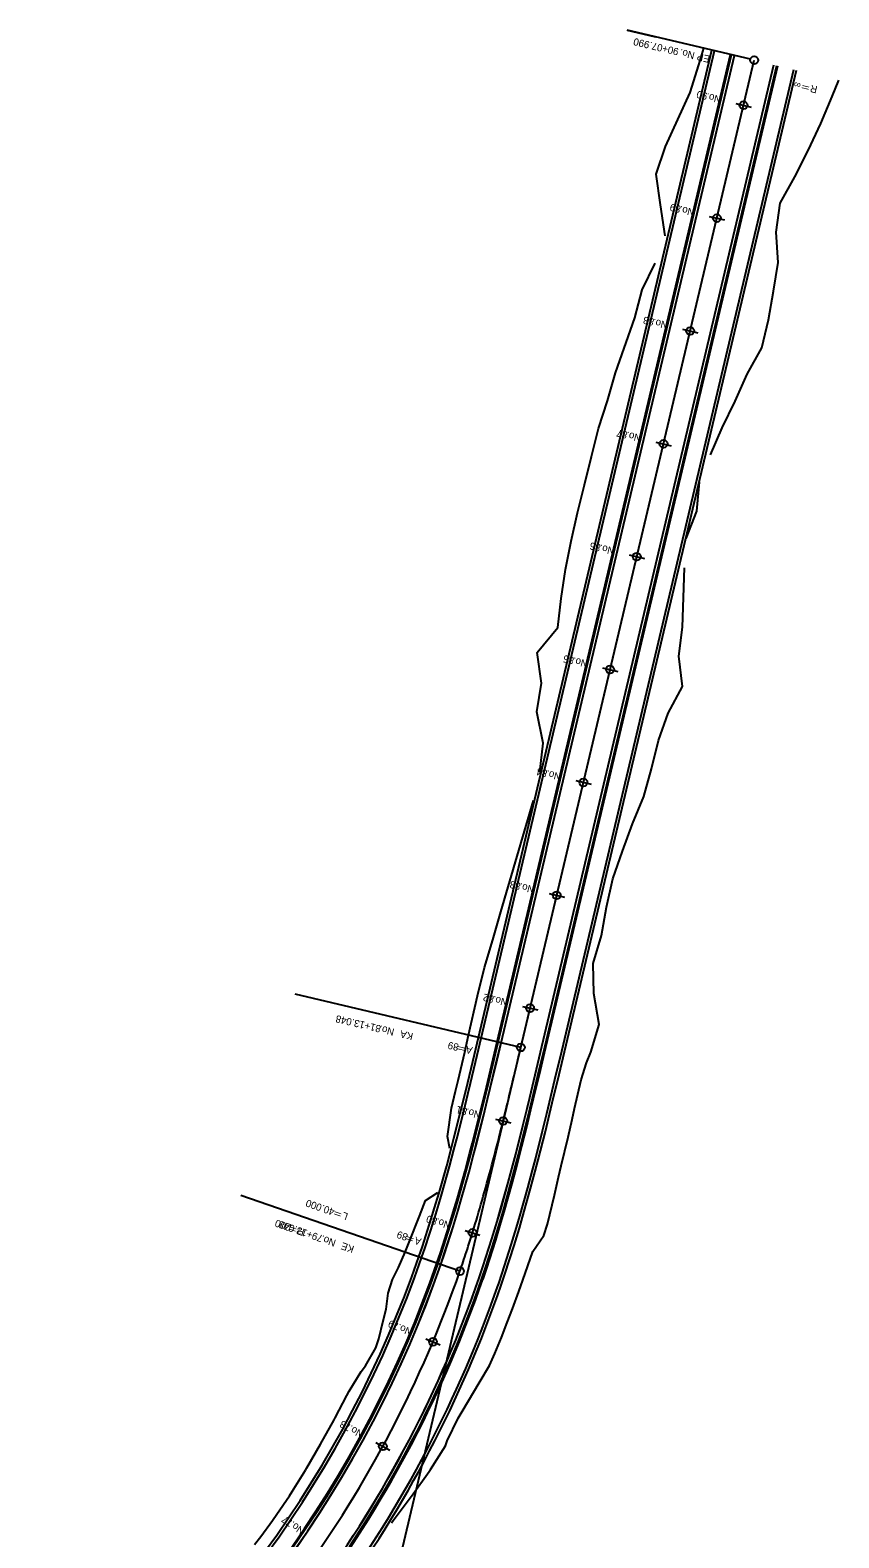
# Model space of a CAD drawing. Extents: x 46424 to 47578, y 10417 to 11548.
# Drawn here: x 47438.6 to 47578.1, y 11288 to 11548 of the extents above; entities that cross this region are included whole.
import ezdxf

# ---------------------------------------------------------------- set-up
doc = ezdxf.new("R2010")
doc.units = 0
for name, color, linetype in [('Default', 7, 'Continuous'), ('出典（地理院地図Vector）', 7, 'Continuous'), ('河川_人工水路(地下)（地理院地図Vector）', 7, 'Continuous'), ('現況_地形', 7, 'Continuous'), ('現況_地形_三角形', 7, 'Continuous'), ('現況_地形_三角形_頂点', 7, 'Continuous'), ('現況_地形_低い点', 7, 'Continuous'), ('現況_地形_単点標高', 7, 'Continuous'), ('現況_地形_等高線_マイナー', 7, 'Continuous'), ('等高線等深線_等高線_補助曲線通常部（地理院地図Vector）', 7, 'Continuous'), ('設計図面_測点 ラベル メジャー', 7, 'Continuous'), ('設計図面_測点 印 メジャー', 7, 'Continuous')]:
    doc.layers.add(name, color=color, linetype=linetype)

msp = doc.modelspace()

# ---------------------------------------------------------------- linework, layer by layer
at = {"layer": 'Default'}
for p, q in [((47562.82, 11542.97), (47541.58, 11547.99)), ((47541.58, 11547.99), (47546.44, 11546.84)), ((47499.18, 11270.82), (47563.47, 11542.81)), ((47523.23, 11372.56), (47563.47, 11542.81)), ((47563.47, 11542.81), (47563.47, 11542.81)), ((47561.64, 11535.04), (47561.64, 11535.04)), ((47557.04, 11515.57), (47557.04, 11515.57)), ((47552.44, 11496.11), (47552.44, 11496.11)), ((47547.84, 11476.65), (47547.84, 11476.65)), ((47543.23, 11457.18), (47543.23, 11457.18)), ((47538.63, 11437.72), (47538.63, 11437.72)), ((47534.03, 11418.25), (47534.03, 11418.25)), ((47529.43, 11398.79), (47529.43, 11398.79)), ((47523.23, 11372.56), (47484.31, 11381.76)), ((47524.83, 11379.33), (47524.83, 11379.33)), ((47523.23, 11372.56), (47523.23, 11372.56)), ((47520.19, 11359.87), (47520.19, 11359.87)), ((47512.74, 11333.98), (47474.93, 11347.02)), ((47512.74, 11333.98), (47474.93, 11347.02)), ((47514.9, 11340.59), (47514.9, 11340.59)), ((47512.74, 11333.98), (47512.74, 11333.98)), ((47508.09, 11321.79), (47508.09, 11321.79)), ((47499.44, 11303.77), (47499.44, 11303.77))]:
    msp.add_line(p, q, dxfattribs=at)
for centre in [(47563.47, 11542.81), (47561.64, 11535.04), (47557.04, 11515.57), (47552.44, 11496.11), (47547.84, 11476.65), (47543.23, 11457.18), (47538.63, 11437.72), (47534.03, 11418.25), (47529.43, 11398.79), (47524.83, 11379.33), (47523.23, 11372.56), (47520.19, 11359.87), (47514.9, 11340.59), (47512.74, 11333.98), (47508.09, 11321.79), (47499.44, 11303.77)]:
    msp.add_circle(centre, 0.675, dxfattribs=at)
msp.add_arc((47323.67, 11399.19), 200, 306.6653, 340.9717, dxfattribs=at)
msp.add_arc((47323.67, 11399.19), 200, 306.6653, 340.9717, dxfattribs=at)
msp.add_open_spline([(47512.74, 11333.98), (47513.11, 11335.03), (47513.81, 11337.14), (47515.16, 11341.37), (47516.74, 11346.7), (47518.49, 11353.13), (47520.13, 11359.59), (47521.44, 11364.99), (47522.47, 11369.32), (47522.98, 11371.48), (47523.23, 11372.56)], degree=3, dxfattribs=at)
msp.add_open_spline([(47512.74, 11333.98), (47513.11, 11335.03), (47513.81, 11337.14), (47515.16, 11341.37), (47516.74, 11346.7), (47518.49, 11353.13), (47520.13, 11359.59), (47521.44, 11364.99), (47522.47, 11369.32), (47522.98, 11371.48), (47523.23, 11372.56)], degree=3, dxfattribs=at)
at = {"layer": '出典（地理院地図Vector）'}
for points in [[(47505.65, 11336.42), (47506.26, 11338.21), (47507.74, 11342.81), (47508.6, 11345.64), (47509.13, 11347.46), (47510.45, 11352.16), (47511.22, 11355.04), (47511.7, 11356.9), (47512.91, 11361.68), (47513.62, 11364.61), (47514.08, 11366.49), (47515.23, 11371.32), (47515.93, 11374.29), (47556.18, 11544.54)], [(47519.83, 11331.53), (47520.49, 11333.45), (47522.07, 11338.37), (47522.98, 11341.37), (47523.54, 11343.3), (47524.92, 11348.23), (47525.72, 11351.23), (47526.22, 11353.15), (47527.47, 11358.07), (47528.2, 11361.06), (47528.66, 11362.98), (47529.83, 11367.87), (47530.53, 11370.84), (47570.77, 11541.09)]]:
    msp.add_lwpolyline(points, dxfattribs=at)
for radius in [192.5, 207.5]:
    msp.add_arc((47323.67, 11399.19), radius, 306.6653, 340.9717, dxfattribs=at)
at = {"layer": '河川_人工水路(地下)（地理院地図Vector）'}
msp.add_line((47523.23, 11372.56), (47563.47, 11542.81), dxfattribs=at)
msp.add_arc((47323.67, 11399.19), 200, 306.6653, 340.9717, dxfattribs=at)
msp.add_open_spline([(47512.74, 11333.98), (47513.11, 11335.03), (47513.81, 11337.14), (47515.16, 11341.37), (47516.74, 11346.7), (47518.49, 11353.13), (47520.13, 11359.59), (47521.44, 11364.99), (47522.47, 11369.32), (47522.98, 11371.48), (47523.23, 11372.56)], degree=3, dxfattribs=at)
at = {"layer": '現況_地形'}
for points in [[(47509.43, 11335.12), (47510.04, 11336.94), (47511.55, 11341.63), (47512.42, 11344.5), (47512.96, 11346.35), (47514.3, 11351.11), (47515.08, 11354.03), (47515.56, 11355.9), (47516.78, 11360.72), (47517.5, 11363.66), (47517.96, 11365.55), (47519.12, 11370.4), (47519.82, 11373.37), (47560.06, 11543.62)], [(47509.44, 11335.12), (47510.05, 11336.94), (47511.56, 11341.62), (47512.43, 11344.5), (47512.97, 11346.35), (47514.31, 11351.11), (47515.09, 11354.03), (47515.57, 11355.9), (47516.79, 11360.72), (47517.51, 11363.66), (47517.97, 11365.55), (47519.13, 11370.4), (47519.83, 11373.37), (47560.07, 11543.62)], [(47516.05, 11332.84), (47516.69, 11334.72), (47518.25, 11339.55), (47519.14, 11342.51), (47519.7, 11344.41), (47521.06, 11349.27), (47521.86, 11352.25), (47522.35, 11354.15), (47523.58, 11359.03), (47524.31, 11362.01), (47524.77, 11363.91), (47525.94, 11368.79), (47526.64, 11371.76), (47566.88, 11542.01)], [(47516.06, 11332.84), (47516.7, 11334.71), (47518.26, 11339.55), (47519.15, 11342.51), (47519.71, 11344.4), (47521.07, 11349.27), (47521.87, 11352.24), (47522.36, 11354.15), (47523.59, 11359.03), (47524.32, 11362.01), (47524.78, 11363.91), (47525.95, 11368.79), (47526.65, 11371.75), (47566.89, 11542)]]:
    msp.add_lwpolyline(points, dxfattribs=at)
for radius in [196.5, 196.49, 203.5, 203.51]:
    msp.add_arc((47323.67, 11399.19), radius, 306.6653, 340.9717, dxfattribs=at)
at = {"layer": '現況_地形_三角形'}
for points in [[(47548.14, 11512.54), (47547.32, 11517.87), (47546.6, 11523.18), (47548.17, 11527.94), (47552.45, 11537.21), (47553.94, 11541.99), (47554.79, 11544.87)], [(47551.75, 11460.31), (47553.57, 11465.01), (47554.02, 11470.05)], [(47510.97, 11355.11), (47510.62, 11357.18), (47511.29, 11362.08), (47512, 11365), (47512.46, 11366.88), (47513.58, 11371.72), (47514.24, 11374.69), (47515.74, 11381.48), (47517, 11386.32), (47518.4, 11391.12), (47519.78, 11395.93), (47525.42, 11415.15)], [(47477.32, 11286.81), (47478.39, 11288.19), (47480.41, 11290.97), (47481.17, 11292.05), (47483.34, 11295.25), (47483.83, 11296), (47486.1, 11299.64), (47486.35, 11300.04), (47488.7, 11304.12), (47491.02, 11308.34), (47491.2, 11308.66), (47493.25, 11312.55), (47493.61, 11313.25), (47495.7, 11316.65), (47496.45, 11317.64), (47498.26, 11320.73), (47498.75, 11322.31), (47499.51, 11325.39), (47500.01, 11327.42), (47500.36, 11330.18), (47501.1, 11332.54), (47502.12, 11334.58), (47503.27, 11337.25), (47503.99, 11338.96), (47505.74, 11343.43), (47506.77, 11346.18), (47508.9, 11347.53)]]:
    msp.add_lwpolyline(points, dxfattribs=at)
at = {"layer": '現況_地形_三角形_頂点'}
for points in [[(47555.92, 11474.73), (47557.98, 11479.39), (47560.18, 11484), (47562.25, 11488.65), (47564.81, 11493.18), (47565.97, 11498.05), (47566.79, 11502.99), (47567.6, 11507.94), (47567.26, 11513.16), (47567.95, 11518.13), (47570.47, 11522.67), (47572.8, 11527.26), (47574.96, 11531.89), (47576.91, 11536.56), (47578.08, 11539.36)], [(47526.5, 11420.04), (47527.09, 11425.03), (47525.98, 11430.43), (47526.8, 11435.38), (47526.06, 11440.69), (47529.6, 11444.99), (47530.22, 11449.98), (47530.93, 11454.95), (47531.91, 11459.86), (47533.03, 11464.73), (47534.22, 11469.59), (47535.41, 11474.45), (47536.62, 11479.3), (47538.18, 11484.07), (47539.54, 11488.88), (47542.9, 11498.36), (47544.15, 11503.2), (47546.41, 11507.81)], [(47500.94, 11290.55), (47501.25, 11290.96), (47504.33, 11295.12), (47504.36, 11295.17), (47507.41, 11299.44), (47507.64, 11299.78), (47510.24, 11303.86), (47510.54, 11304.69), (47512.41, 11308.63), (47513.13, 11309.77), (47515.14, 11313.14), (47516.04, 11314.72), (47517.83, 11317.7), (47518.74, 11319.79), (47519.89, 11322.55), (47520.9, 11325.1), (47521.81, 11327.46), (47522.92, 11330.47), (47523.61, 11332.41), (47525.3, 11337.37), (47527.22, 11340.11), (47527.86, 11342.05), (47529.05, 11347.1), (47529.75, 11350.17), (47530.22, 11352.12), (47531.38, 11357.1), (47532.08, 11360.12), (47532.52, 11362.05), (47533.63, 11366.97), (47534.56, 11369.88), (47535.33, 11371.71), (47536.73, 11376.51), (47535.82, 11381.87), (47535.7, 11387.03), (47537.12, 11391.84), (47538.02, 11396.76), (47539.12, 11401.64), (47540.77, 11406.39), (47542.5, 11411.12), (47544.42, 11415.8), (47545.77, 11420.62), (47547, 11425.47), (47548.67, 11430.21), (47551.12, 11434.77), (47550.51, 11440.05), (47551.11, 11445.05), (47551.45, 11455.24)]]:
    msp.add_lwpolyline(points, dxfattribs=at)
at = {"layer": '現況_地形_低い点'}
for points in [[(47508.96, 11335.28), (47509.58, 11337.1), (47511.08, 11341.77), (47511.95, 11344.64), (47512.49, 11346.49), (47513.82, 11351.24), (47514.6, 11354.15), (47515.09, 11356.03), (47516.3, 11360.84), (47517.03, 11363.78), (47517.48, 11365.67), (47518.64, 11370.52), (47519.34, 11373.48), (47559.58, 11543.73)], [(47516.53, 11332.68), (47517.17, 11334.56), (47518.72, 11339.4), (47519.62, 11342.37), (47520.18, 11344.27), (47521.54, 11349.14), (47522.34, 11352.12), (47522.84, 11354.03), (47524.07, 11358.91), (47524.8, 11361.89), (47525.26, 11363.8), (47526.42, 11368.67), (47527.13, 11371.64), (47567.37, 11541.89)]]:
    msp.add_lwpolyline(points, dxfattribs=at)
for radius in [196, 204]:
    msp.add_arc((47323.67, 11399.19), radius, 306.6653, 340.9717, dxfattribs=at)
at = {"layer": '現況_地形_単点標高'}
for points in [[(47506.13, 11336.26), (47506.73, 11338.05), (47508.22, 11342.66), (47509.08, 11345.5), (47509.61, 11347.32), (47510.93, 11352.03), (47511.7, 11354.92), (47512.18, 11356.77), (47513.39, 11361.56), (47514.11, 11364.49), (47514.57, 11366.37), (47515.72, 11371.21), (47516.42, 11374.17), (47556.66, 11544.42)], [(47508.77, 11335.35), (47509.39, 11337.16), (47510.89, 11341.83), (47511.76, 11344.7), (47512.3, 11346.54), (47513.63, 11351.29), (47514.41, 11354.21), (47514.9, 11356.08), (47516.11, 11360.88), (47516.83, 11363.83), (47517.29, 11365.71), (47518.44, 11370.56), (47519.15, 11373.53), (47559.39, 11543.78)], [(47516.72, 11332.61), (47517.36, 11334.5), (47518.92, 11339.34), (47519.81, 11342.31), (47520.37, 11344.21), (47521.74, 11349.09), (47522.53, 11352.07), (47523.03, 11353.98), (47524.26, 11358.86), (47524.99, 11361.84), (47525.45, 11363.75), (47526.62, 11368.63), (47527.32, 11371.6), (47567.56, 11541.85)], [(47519.36, 11331.7), (47520.01, 11333.61), (47521.59, 11338.52), (47522.5, 11341.51), (47523.06, 11343.43), (47524.44, 11348.36), (47525.24, 11351.36), (47525.74, 11353.28), (47526.98, 11358.19), (47527.71, 11361.18), (47528.18, 11363.09), (47529.34, 11367.98), (47530.05, 11370.95), (47570.29, 11541.2)]]:
    msp.add_lwpolyline(points, dxfattribs=at)
for radius in [193, 195.8, 204.2, 207]:
    msp.add_arc((47323.67, 11399.19), radius, 306.6653, 340.9717, dxfattribs=at)
at = {"layer": '現況_地形_等高線_マイナー'}
for points in [[(47508.94, 11335.29), (47509.56, 11337.1), (47511.06, 11341.78), (47511.93, 11344.65), (47512.47, 11346.49), (47513.8, 11351.25), (47514.58, 11354.16), (47515.07, 11356.03), (47516.28, 11360.84), (47517.01, 11363.78), (47517.46, 11365.67), (47518.62, 11370.52), (47519.32, 11373.49), (47559.56, 11543.74)], [(47516.55, 11332.67), (47517.18, 11334.55), (47518.74, 11339.4), (47519.64, 11342.36), (47520.2, 11344.26), (47521.56, 11349.14), (47522.36, 11352.12), (47522.86, 11354.02), (47524.09, 11358.91), (47524.82, 11361.89), (47525.28, 11363.79), (47526.44, 11368.67), (47527.15, 11371.64), (47567.39, 11541.89)]]:
    msp.add_lwpolyline(points, dxfattribs=at)
for radius in [195.98, 204.02]:
    msp.add_arc((47323.67, 11399.19), radius, 306.6653, 340.9717, dxfattribs=at)
at = {"layer": '等高線等深線_等高線_補助曲線通常部（地理院地図Vector）'}
msp.add_line((47523.23, 11372.56), (47563.47, 11542.81), dxfattribs=at)
msp.add_arc((47323.67, 11399.19), 200, 306.6653, 340.9717, dxfattribs=at)
msp.add_open_spline([(47512.74, 11333.98), (47513.11, 11335.03), (47513.81, 11337.14), (47515.16, 11341.37), (47516.74, 11346.7), (47518.49, 11353.13), (47520.13, 11359.59), (47521.44, 11364.99), (47522.47, 11369.32), (47522.98, 11371.48), (47523.23, 11372.56)], degree=3, dxfattribs=at)
at = {"layer": '設計図面_測点 印 メジャー'}
for p, q in [((47560.32, 11535.35), (47562.95, 11534.73)), ((47555.72, 11515.88), (47558.35, 11515.26)), ((47551.12, 11496.42), (47553.75, 11495.8)), ((47546.52, 11476.96), (47549.15, 11476.33)), ((47541.92, 11457.49), (47544.55, 11456.87)), ((47537.32, 11438.03), (47539.95, 11437.41)), ((47532.72, 11418.56), (47535.35, 11417.94)), ((47528.12, 11399.1), (47530.75, 11398.48)), ((47523.52, 11379.64), (47526.15, 11379.02)), ((47518.88, 11360.2), (47521.5, 11359.55)), ((47513.61, 11340.99), (47516.19, 11340.19)), ((47506.85, 11322.31), (47509.34, 11321.27)), ((47498.26, 11304.41), (47500.63, 11303.12))]:
    msp.add_line(p, q, dxfattribs=at)

# ---------------------------------------------------------------- texts
at = {"layer": 'Default'}
for s, rotation, p in [('90+07.990', 166.7013, (47550.56, 11544.82)), ('EP No.', 166.7013, (47555.94, 11543.54)), ('R＝∞', 166.7013, (47574.47, 11538.29)), ('81+13.048', 166.7013, (47499.22, 11376.31)), ('\u3000No.', 166.7013, (47503.17, 11375.38)), ('KA', 166.7013, (47504.76, 11375)), ('89', 166.7013, (47512.63, 11373.14)), ('A＝', 166.7013, (47515, 11372.58)), ('40.000', 160.9717, (47491.25, 11344.7)), ('L＝', 160.9717, (47493.55, 11343.9)), ('200', 160.9717, (47483.74, 11342)), ('79+13.048', 160.9717, (47489.23, 11340.11)), ('R＝', 160.9717, (47486.05, 11341.2)), ('\u3000No.', 160.9717, (47493.07, 11338.78)), ('KE', 160.9717, (47494.6, 11338.25)), ('89', 160.9717, (47503.88, 11340.34)), ('A＝', 160.9717, (47506.18, 11339.55))]:
    msp.add_text(s, height=1.25, rotation=rotation, dxfattribs=at).set_placement(p)
at = {"layer": '設計図面_測点 ラベル メジャー'}
for s, rotation, p in [('90', 166.7013, (47555.52, 11537.13)), ('No.', 166.7013, (47557.89, 11536.56)), ('89', 166.7013, (47550.92, 11517.66)), ('No.', 166.7013, (47553.29, 11517.1)), ('88', 166.7013, (47546.32, 11498.2)), ('No.', 166.7013, (47548.69, 11497.64)), ('87', 166.7013, (47541.72, 11478.73)), ('No.', 166.7013, (47544.09, 11478.17)), ('86', 166.7013, (47537.11, 11459.27)), ('No.', 166.7013, (47539.49, 11458.71)), ('85', 166.7013, (47532.51, 11439.81)), ('No.', 166.7013, (47534.89, 11439.25)), ('84', 166.7013, (47527.91, 11420.34)), ('No.', 166.7013, (47530.28, 11419.78)), ('83', 166.7013, (47523.31, 11400.88)), ('No.', 166.7013, (47525.68, 11400.32)), ('82', 166.7013, (47518.71, 11381.42)), ('No.', 166.7013, (47521.08, 11380.86)), ('81', 166.0916, (47514.09, 11362.03)), ('No.', 166.0916, (47516.45, 11361.44)), ('80', 162.7902, (47508.94, 11343.09)), ('No.', 162.7902, (47511.27, 11342.37)), ('79', 157.2337, (47502.4, 11324.86)), ('No.', 157.2337, (47504.64, 11323.92)), ('78', 151.5041, (47494.08, 11307.39)), ('No.', 151.5041, (47496.23, 11306.23)), ('77', 145.7745, (47484.07, 11290.83)), ('No.', 145.7745, (47486.08, 11289.46))]:
    msp.add_text(s, height=1.25, rotation=rotation, dxfattribs=at).set_placement(p)

doc.saveas('drawing.dxf')
